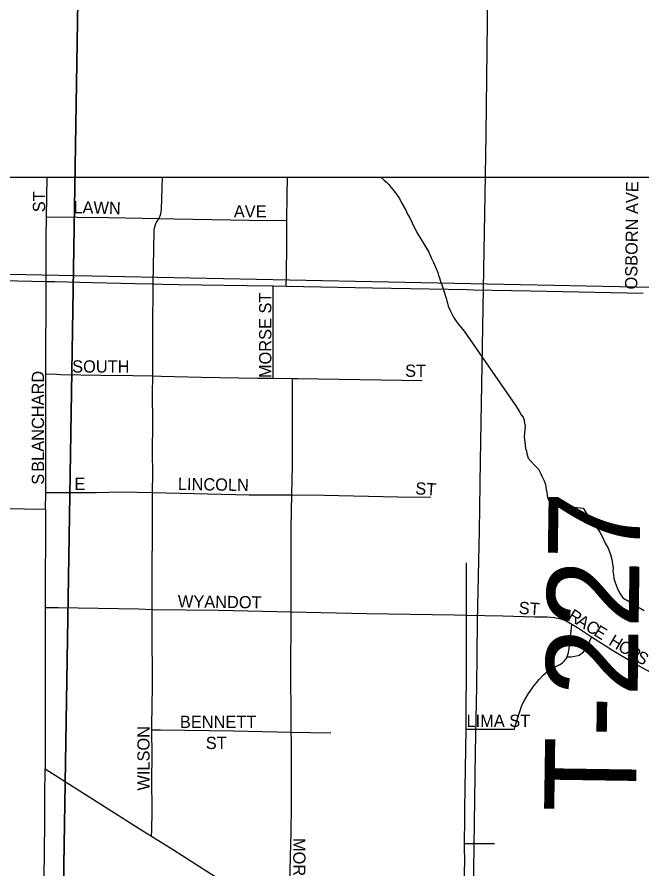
# Model space of a CAD drawing. Extents: x 0 to 68, y 0 to 52.9.
# Drawn here: x 44.415 to 44.925, y 37.97 to 38.666 of the extents above; entities that cross this region are included whole.
import ezdxf

# ---------------------------------------------------------------- set-up
doc = ezdxf.new("R2010")
doc.units = 0
for name, color, linetype in [('Default', 7, 'Continuous'), ('GM_X_Minor_River', 7, 'Continuous'), ('GM_X_State_Route', 7, 'Continuous'), ('GM_X_Township_Road', 7, 'Continuous'), ('GM_X_Township_Road_Text', 7, 'Continuous')]:
    doc.layers.add(name, color=color, linetype=linetype)

msp = doc.modelspace()

# ---------------------------------------------------------------- linework, layer by layer
at = {"layer": 'Default'}
msp.add_line((42.25806, 38.53508), (49.65006, 38.53508), dxfattribs=at)
for points in [[(43.1609, 39.26536), (44.47349, 39.25009), (44.45233, 37.93902), (44.41032, 37.93957), (43.13273, 37.95279)], [(45.79985, 39.21605), (45.7821, 37.90702), (45.7586, 37.9073), (44.45233, 37.93902), (44.47349, 39.25009)], [(43.93627, 38.46518), (44.96064, 38.44451), (44.96032, 37.38586), (43.92065, 37.39833), (43.9204, 37.41034)]]:
    msp.add_lwpolyline(points, close=True, dxfattribs=at)
for points in [[(44.43878, 38.50266), (44.43935, 38.53508)], [(44.53054, 38.50132), (44.53162, 38.50348), (44.53204, 38.50493), (44.53235, 38.50631), (44.53245, 38.50689), (44.53265, 38.5086), (44.53337, 38.53508)], [(44.63506, 38.49977), (44.6354, 38.51993), (44.63564, 38.53508)], [(44.43845, 38.44987), (44.43856, 38.48531), (44.43878, 38.50266)], [(44.43878, 38.50266), (44.48922, 38.5019), (44.53054, 38.50132)], [(44.52573, 38.44776), (44.52655, 38.49051), (44.52657, 38.49159), (44.52688, 38.49355), (44.52735, 38.49524), (44.52802, 38.49706), (44.5284, 38.4978), (44.52924, 38.49922), (44.53054, 38.50132)], [(44.53054, 38.50132), (44.5431, 38.50106), (44.61914, 38.49968), (44.63506, 38.49977)], [(44.63454, 38.44599), (44.63468, 38.45432), (44.63513, 38.48062), (44.63506, 38.49977)], [(44.4383, 38.37434), (44.43845, 38.44987)], [(44.52544, 38.37255), (44.52544, 38.41029), (44.52573, 38.44776)], [(44.62382, 38.37063), (44.62386, 38.37833), (44.62397, 38.39787), (44.62387, 38.41035), (44.62388, 38.43322), (44.62387, 38.44267), (44.62387, 38.44619)], [(44.43805, 38.27726), (44.43821, 38.32535), (44.4383, 38.37434)], [(44.4383, 38.37434), (44.44687, 38.37398), (44.45015, 38.37384), (44.48301, 38.37318), (44.50929, 38.3729), (44.52544, 38.37255)], [(44.52541, 38.27747), (44.52546, 38.29307), (44.52527, 38.30949), (44.52552, 38.33493), (44.5254, 38.35789), (44.52544, 38.37255)], [(44.52544, 38.37255), (44.53227, 38.3724), (44.56511, 38.37169), (44.61108, 38.37073), (44.62382, 38.37063)], [(44.62382, 38.37063), (44.63956, 38.37051)], [(44.63906, 38.27539), (44.63956, 38.29978), (44.63956, 38.36289), (44.63956, 38.37051)], [(44.63956, 38.37051), (44.6439, 38.37048), (44.7456, 38.36878)], [(44.43805, 38.27726), (44.44701, 38.27726), (44.47956, 38.27727), (44.49965, 38.27776), (44.52541, 38.27747)], [(44.52511, 38.18169), (44.52541, 38.27747)], [(44.52541, 38.27747), (44.60431, 38.27546), (44.63906, 38.27539)], [(44.43779, 38.26365), (44.43805, 38.27726)], [(44.6385, 38.17985), (44.63851, 38.24861), (44.63906, 38.27539)], [(44.63906, 38.27539), (44.66537, 38.27529), (44.72567, 38.27382), (44.75266, 38.27344)], [(44.78184, 38.17716), (44.78186, 38.21993)], [(44.43762, 38.18349), (44.44826, 38.18331), (44.51378, 38.18216), (44.52511, 38.18169)], [(44.52476, 38.08339), (44.52471, 38.09182), (44.52508, 38.09802), (44.52531, 38.1238), (44.52503, 38.16312), (44.52511, 38.18169)], [(44.52511, 38.18169), (44.57934, 38.18109), (44.6385, 38.17985)], [(44.63854, 38.0814), (44.63862, 38.08995), (44.63824, 38.13407), (44.63841, 38.17232), (44.6385, 38.17985)], [(44.6385, 38.17985), (44.70008, 38.17856), (44.77193, 38.17744), (44.78184, 38.17716)], [(44.78148, 38.08395), (44.78166, 38.14571), (44.78184, 38.17716)], [(44.78184, 38.17716), (44.8114, 38.17644), (44.83753, 38.17587), (44.84229, 38.17577), (44.84771, 38.17568), (44.85332, 38.17515), (44.85669, 38.17464), (44.85955, 38.17393), (44.86175, 38.1731)], [(44.86774, 38.16957), (44.86175, 38.1731)], [(44.86405, 38.14309), (44.86509, 38.14649), (44.86571, 38.14979), (44.86644, 38.15655), (44.86698, 38.16194), (44.86761, 38.16678), (44.86774, 38.16957)], [(44.88387, 38.15922), (44.87252, 38.16675), (44.86774, 38.16957)], [(44.86405, 38.14309), (44.8673, 38.14319), (44.87032, 38.1436), (44.87259, 38.14402), (44.87383, 38.14449), (44.87493, 38.14518), (44.87624, 38.14621), (44.87734, 38.14725), (44.87858, 38.14876), (44.88015, 38.15124), (44.88201, 38.15482), (44.88387, 38.15922)], [(44.96095, 38.11467), (44.95771, 38.11673), (44.94837, 38.12157), (44.93164, 38.13065), (44.9178, 38.13821), (44.90088, 38.14828), (44.88387, 38.15922)], [(44.82088, 38.08383), (44.82173, 38.08715), (44.82439, 38.09604), (44.82665, 38.10241), (44.8276, 38.10459), (44.82845, 38.10658), (44.83248, 38.11306), (44.83691, 38.11956), (44.84102, 38.12468), (44.84466, 38.12845), (44.84819, 38.13138), (44.84956, 38.13232), (44.85154, 38.13344), (44.85799, 38.13669), (44.86016, 38.13816), (44.86159, 38.1395), (44.86242, 38.1405), (44.8632, 38.14156), (44.86396, 38.14289), (44.86405, 38.14309)], [(44.52453, 37.99646), (44.52462, 38.00121), (44.52491, 38.01731), (44.52479, 38.04274), (44.52488, 38.06225), (44.52476, 38.08339)], [(44.52476, 38.08339), (44.53194, 38.08331), (44.59147, 38.08266), (44.63854, 38.0814)], [(44.78014, 37.99056), (44.7804, 38.01078), (44.78049, 38.01921), (44.78148, 38.08395)], [(44.78148, 38.08395), (44.7881, 38.08394), (44.79828, 38.08393), (44.82088, 38.08383)], [(44.63484, 37.92679), (44.63585, 37.92946), (44.63699, 37.93323), (44.63703, 37.93498), (44.63731, 37.94701), (44.63811, 37.97967), (44.63852, 37.99959), (44.63871, 38.02121), (44.63881, 38.07442), (44.63854, 38.0814)], [(44.63854, 38.0814), (44.67103, 38.08087)], [(44.43533, 37.78123), (44.43536, 37.78496), (44.43555, 37.82108), (44.43597, 37.85053), (44.43607, 37.89319), (44.43648, 37.93913), (44.43704, 37.9848), (44.4374, 38.00679), (44.43731, 38.02977), (44.43752, 38.05165)], [(44.77962, 37.83631), (44.77965, 37.84375), (44.77967, 37.84635), (44.77965, 37.87219), (44.77965, 37.88197), (44.77985, 37.93041), (44.77993, 37.94854), (44.78032, 37.97938), (44.78019, 37.98435), (44.78014, 37.99056)], [(44.78014, 37.99056), (44.78427, 37.99068), (44.79268, 37.99042), (44.8045, 37.99048)]]:
    msp.add_lwpolyline(points, dxfattribs=at)
at = {"layer": 'GM_X_Minor_River'}
for points in [[(44.71156, 38.53508), (44.71164, 38.53502), (44.7144, 38.53255), (44.71637, 38.53091), (44.71834, 38.52887), (44.7199, 38.52683), (44.72146, 38.52479), (44.72342, 38.52234), (44.72498, 38.52031), (44.72693, 38.51746), (44.72848, 38.51462), (44.73042, 38.51137), (44.73197, 38.50853), (44.7335, 38.50489), (44.73544, 38.50164), (44.73737, 38.49759), (44.73929, 38.49354), (44.74161, 38.48908), (44.7486, 38.4777), (44.75093, 38.47364), (44.75284, 38.46919), (44.75477, 38.46514), (44.7563, 38.4615), (44.75821, 38.45705), (44.75897, 38.45462), (44.75973, 38.4526), (44.76048, 38.44978), (44.76162, 38.44695), (44.76276, 38.44372), (44.76351, 38.44129), (44.76426, 38.43847), (44.76501, 38.43605), (44.76577, 38.43402), (44.76614, 38.43201)], [(44.76614, 38.43201), (44.76689, 38.42959), (44.76842, 38.42595), (44.76958, 38.42392), (44.77112, 38.42068), (44.77268, 38.41824), (44.77463, 38.41539), (44.77994, 38.40917)], [(44.77994, 38.40917), (44.82191, 38.34815)], [(44.82191, 38.34815), (44.82261, 38.34742), (44.82494, 38.34336), (44.82649, 38.34092), (44.82806, 38.33889), (44.82881, 38.33646), (44.82916, 38.33405), (44.82952, 38.33163), (44.82945, 38.32843), (44.829, 38.32603), (44.82894, 38.32282), (44.8296, 38.31599), (44.82994, 38.31317), (44.8307, 38.31115), (44.83106, 38.30914), (44.8322, 38.3055), (44.83415, 38.30306), (44.8373, 38.29978), (44.84044, 38.29651), (44.84237, 38.29246), (44.84352, 38.29003), (44.84506, 38.28679), (44.84621, 38.28396), (44.84657, 38.28194), (44.84692, 38.27953), (44.84728, 38.27751), (44.84764, 38.2755), (44.84799, 38.27309), (44.84953, 38.26985), (44.85149, 38.2674), (44.85229, 38.26738), (44.87711, 38.26448)], [(44.87711, 38.26448), (44.88294, 38.25513), (44.88569, 38.25187), (44.88842, 38.2482), (44.89076, 38.24494), (44.89269, 38.24089), (44.895, 38.23603), (44.89733, 38.23197), (44.89922, 38.22672), (44.90035, 38.22268), (44.90107, 38.21906), (44.9014, 38.21544), (44.90135, 38.21303), (44.9017, 38.21022), (44.90204, 38.207), (44.90317, 38.20377), (44.90469, 38.19933), (44.90661, 38.19528), (44.90934, 38.19121), (44.9145, 38.1883), (44.91926, 38.18539), (44.92362, 38.1829), (44.92679, 38.18083)]]:
    msp.add_lwpolyline(points, dxfattribs=at)
at = {"layer": 'GM_X_State_Route'}
for points in [[(44.12946, 38.46411), (44.15301, 38.46346), (44.17714, 38.46274), (44.21961, 38.46145), (44.26368, 38.45917), (44.27511, 38.45858), (44.31751, 38.4558), (44.34682, 38.45337), (44.3664, 38.45171), (44.37952, 38.45117), (44.43845, 38.44987), (44.44553, 38.44971), (44.47631, 38.44893)], [(44.47631, 38.44893), (44.51104, 38.44805), (44.52573, 38.44776), (44.5334, 38.44764), (44.54658, 38.44735), (44.60265, 38.44659), (44.62387, 38.44619)], [(44.62387, 38.44619), (44.63454, 38.44599), (44.70488, 38.44466), (44.7824, 38.44312)], [(44.7824, 38.44312), (44.78733, 38.44302), (44.83389, 38.44209), (44.92603, 38.44031)], [(43.93727, 38.27455), (43.95751, 38.27431), (44.00666, 38.27323), (44.0338, 38.27257), (44.09838, 38.27099), (44.12639, 38.27017), (44.1441, 38.26931), (44.26199, 38.26653), (44.29804, 38.26568), (44.33408, 38.26543), (44.43779, 38.26365)], [(44.43779, 38.26365), (44.43762, 38.18349), (44.43752, 38.05376)], [(44.43752, 38.05376), (44.43752, 38.05165), (44.51728, 38.00099), (44.52453, 37.99646), (44.54231, 37.98537), (44.58338, 37.95928)]]:
    msp.add_lwpolyline(points, dxfattribs=at)
at = {"layer": 'GM_X_Township_Road'}
msp.add_lwpolyline([(44.7872, 37.93047), (44.78916, 38.0655), (44.79016, 38.11876), (44.79071, 38.17209), (44.79244, 38.2459), (44.79316, 38.30333), (44.79602, 38.45915), (44.79696, 38.52068), (44.79793, 38.56987), (44.79919, 38.6847), (44.79993, 38.77083), (44.80072, 38.85276), (44.80196, 38.93851), (44.80314, 39.05312), (44.80377, 39.09415), (44.80406, 39.13866), (44.8054, 39.1908), (44.80605, 39.24618)], dxfattribs=at)

# ---------------------------------------------------------------- texts
at = {"layer": 'Default'}
for s, rotation, p in [('OSBORN AVE', 89.3493, (44.92115, 38.44316)), ('ST', 90, (44.43757, 38.50634)), ('LAWN', 358.63682, (44.46062, 38.50558)), ('AVE', 0.00001, (44.5917, 38.50206)), ('MORSE ST', 90, (44.62237, 38.37082)), ('SOUTH', 0.00001, (44.45969, 38.37534)), ('ST', 0.00001, (44.73162, 38.37182)), ('BLANCHARD', 90, (44.4367, 38.29426)), ('S', 90, (44.4367, 38.2837)), ('E', 0.00001, (44.46145, 38.27942)), ('LINCOLN', 359.06134, (44.54596, 38.27942)), ('ST', 356.18786, (44.73966, 38.2759)), ('WYANDOT', 359.20474, (44.54596, 38.1835)), ('ST', 356.18786, (44.82414, 38.17822)), ('R', 326.97003, (44.8638, 38.17437)), ('A', 328.19133, (44.87064, 38.16993)), ('C', 328.39439, (44.87815, 38.16527)), ('E', 328.39742, (44.8849, 38.16112)), ('H', 329.09998, (44.89714, 38.15331)), ('O', 329.09896, (44.90469, 38.14879)), ('R', 329.1156, (44.91224, 38.14427)), ('S', 329.09248, (44.91904, 38.14021)), ('BENNETT', 0.00001, (44.54769, 38.08494)), ('LIMA ST', 0.00001, (44.78178, 38.08582)), ('WILSON', 90, (44.52293, 38.03378)), ('ST', 0.00001, (44.56882, 38.06774)), ('MORSE ST', 270, (44.64022, 37.99506))]:
    msp.add_text(s, height=0.01, rotation=rotation, dxfattribs=at).set_placement(p)
at = {"layer": 'GM_X_Township_Road_Text'}
msp.add_text('T-227', height=0.075, rotation=89.15951, dxfattribs=at).set_placement((44.92006, 38.0157))

doc.saveas('drawing.dxf')
